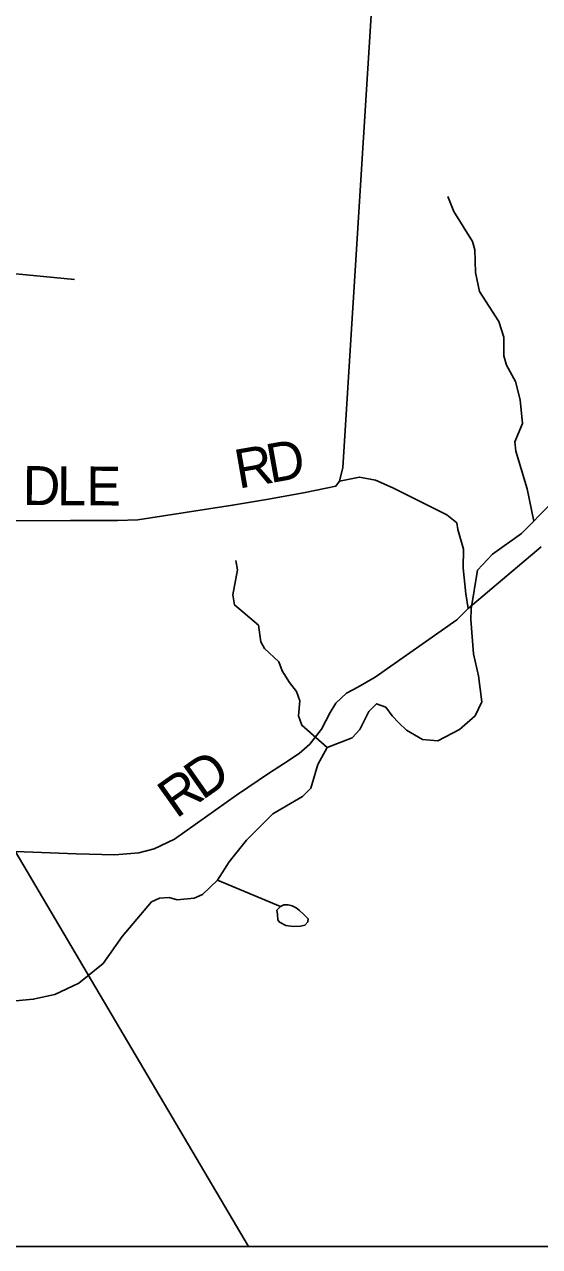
# Model space of a CAD drawing. Extents: x 0 to 48.6, y 0 to 22.
# Drawn here: x 4.768 to 5.519, y 14.1 to 15.882 of the extents above; entities that cross this region are included whole.
import ezdxf

# ---------------------------------------------------------------- set-up
doc = ezdxf.new("R2010")
doc.units = 0
for name, color, linetype in [('GM_X_Corporation', 7, 'Continuous'), ('GM_X_County_Road', 7, 'Continuous'), ('GM_X_County_Road_Text', 7, 'Continuous'), ('GM_X_Minor_Lake', 7, 'Continuous'), ('GM_X_Minor_River', 7, 'Continuous'), ('GM_X_Township_Road', 7, 'Continuous'), ('SH_Data', 7, 'Continuous')]:
    doc.layers.add(name, color=color, linetype=linetype)

msp = doc.modelspace()

# ---------------------------------------------------------------- linework, layer by layer
at = {"layer": 'GM_X_Corporation'}
msp.add_lwpolyline([(5.0944, 14.1), (8.9, 14.1), (8.9, 19.5692), (8.5348, 19.2897), (7.2261, 18.2847), (6.9471, 18.0777), (6.5365, 17.7727), (5.8387, 17.2541), (5.5264, 17.0064), (4.6225, 16.3345), (4.044, 15.9033), (4.0346, 15.8959), (4.0398, 15.887), (4.3544, 15.3539), (4.4679, 15.1616), (4.7542, 14.6766)], close=True, dxfattribs=at)
at = {"layer": 'GM_X_County_Road'}
for points in [[(4.6086, 15.1588), (4.64, 15.1582), (4.8348, 15.1585), (4.9035, 15.1586), (4.9331, 15.1596), (5.071, 15.181), (5.1203, 15.1895), (5.1743, 15.1992), (5.2077, 15.2059), (5.2218, 15.2088), (5.2271, 15.216), (5.2317, 15.2361), (5.2617, 15.7172), (5.2803, 16.0116), (5.7212, 16.011), (6.0742, 16.1743), (6.2545, 16.2661)], [(4.8433, 14.6729), (4.8993, 14.671), (4.9345, 14.6742), (4.9567, 14.68), (4.9863, 14.6941), (5.0766, 14.7581), (5.1247, 14.7908), (5.1451, 14.804), (5.1683, 14.819), (5.1838, 14.8328), (5.2009, 14.8543), (5.2131, 14.8787), (5.2214, 14.8925), (5.2369, 14.9069), (5.2535, 14.9157), (5.2789, 14.9301), (5.3979, 15.0141), (5.4143, 15.0302), (5.5209, 15.1202)], [(4.7544, 14.676), (4.8433, 14.6729)]]:
    msp.add_lwpolyline(points, dxfattribs=at)
at = {"layer": 'GM_X_Minor_Lake'}
for points in [[(5.146, 14.5984), (5.141, 14.5958), (5.1356, 14.5903), (5.1364, 14.5843), (5.1369, 14.5766), (5.1394, 14.5731), (5.1485, 14.5684), (5.1594, 14.5667), (5.1701, 14.5672), (5.1765, 14.5686), (5.1808, 14.5735), (5.1813, 14.578), (5.1746, 14.5846), (5.1686, 14.59), (5.1638, 14.5939), (5.1581, 14.597), (5.1521, 14.5983)], [(5.1521, 14.5983), (5.146, 14.5984)]]:
    msp.add_lwpolyline(points, dxfattribs=at)
at = {"layer": 'GM_X_Minor_River'}
for points in [[(5.5104, 15.158), (5.5003, 15.2047), (5.4839, 15.2596), (5.4825, 15.2733), (5.4939, 15.3004), (5.4905, 15.3346), (5.4837, 15.3616), (5.4703, 15.3853), (5.4663, 15.399), (5.4663, 15.426), (5.4594, 15.4488), (5.4311, 15.4928), (5.425, 15.5202), (5.4243, 15.5532), (5.421, 15.5658), (5.3935, 15.6094), (5.385, 15.6311)], [(4.7247, 15.5215), (4.8406, 15.5102)], [(5.8065, 15.4469), (5.799, 15.4299), (5.7888, 15.3663), (5.78, 15.3345), (5.7595, 15.3067), (5.7469, 15.2997), (5.7237, 15.2935), (5.6575, 15.2761), (5.5961, 15.2514), (5.5754, 15.2334), (5.5526, 15.2071), (5.5356, 15.1834), (5.4922, 15.1396), (5.4501, 15.1097), (5.4282, 15.0865), (5.4191, 15.0301), (5.4185, 15.0145), (5.4221, 14.9644), (5.4296, 14.932)], [(5.1542, 14.9227), (5.1433, 14.9393), (5.1385, 14.9526), (5.1175, 14.9722), (5.1123, 14.9818), (5.1089, 15.0061), (5.0739, 15.0357), (5.0715, 15.0502), (5.0784, 15.0869), (5.0759, 15.1006)], [(4.7544, 14.4583), (4.7806, 14.4605), (4.8122, 14.4674), (4.8471, 14.4842), (4.8825, 14.5128), (4.9099, 14.5521), (4.953, 14.6029), (4.9644, 14.608), (4.9785, 14.6092), (4.9902, 14.6056), (5.0149, 14.6081), (5.0272, 14.6132), (5.0492, 14.6344), (5.066, 14.661), (5.0913, 14.6924), (5.1296, 14.7312), (5.173, 14.7561), (5.185, 14.7684), (5.1952, 14.8028), (5.2089, 14.8279), (5.2453, 14.842), (5.2565, 14.8539), (5.2699, 14.8803), (5.2811, 14.8914), (5.2943, 14.8866), (5.3039, 14.8739), (5.3132, 14.8639), (5.3248, 14.853), (5.348, 14.8393), (5.3704, 14.8373), (5.4018, 14.8538), (5.4246, 14.8739), (5.4345, 14.8942), (5.4296, 14.932)], [(5.2089, 14.8279), (5.172, 14.8601), (5.1673, 14.8739), (5.1689, 14.8959), (5.1642, 14.9092), (5.1542, 14.9227)], [(5.0492, 14.6344), (5.141, 14.5958)]]:
    msp.add_lwpolyline(points, dxfattribs=at)
at = {"layer": 'GM_X_Township_Road'}
msp.add_lwpolyline([(5.4143, 15.0302), (5.411, 15.0518), (5.4071, 15.0894), (5.4077, 15.117), (5.3992, 15.1458), (5.3981, 15.1553), (5.3833, 15.1672), (5.3049, 15.2063), (5.2795, 15.2174), (5.256, 15.2221), (5.2271, 15.216)], dxfattribs=at)
at = {"layer": 'SH_Data'}
msp.add_line((2.1, 14.1), (8.9, 14.1), dxfattribs=at)

# ---------------------------------------------------------------- texts
at = {"layer": 'GM_X_County_Road_Text'}
for s, rotation, p in [('D', 10.2002, (5.126, 15.2131)), ('R', 9.8922, (5.0797, 15.205)), ('D', 359.5483, (4.765, 15.1814)), ('L', 359.563, (4.815, 15.181)), ('E', 359.849, (4.8578, 15.1807)), ('D', 35.0339, (5.0269, 14.7501)), ('R', 35.4147, (4.9889, 14.7231))]:
    msp.add_text(s, height=0.0568, rotation=rotation, dxfattribs=at).set_placement(p)

doc.saveas('drawing.dxf')
